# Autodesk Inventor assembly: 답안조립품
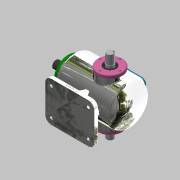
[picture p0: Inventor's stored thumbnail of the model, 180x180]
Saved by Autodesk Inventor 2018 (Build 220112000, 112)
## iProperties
Created: 2021-11
Part Number: 답안조립품
Material: 일반
Document SubType Name: Assembly
Designer: home
Author: home
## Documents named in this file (15)
- C:\Users\home\Desktop\711106V1040\답안조립품.iam
- C:\Users\home\Desktop\711106V1040\본체.ipt
- C:\Users\home\Desktop\711106V1040\슬라이드 커버.ipt
- C:\Users\home\Desktop\711106V1040\슬라이드.ipt
- C:\Users\home\Desktop\711106V1040\부시.ipt
- C:\Users\home\Desktop\711106V1040\상부커버.ipt
- C:\Users\home\Desktop\711106V1040\축 커버.ipt
- C:\Users\home\Desktop\711106V1040\베어링 6205.ipt
- 베어링 6205.ipt
- C:\Users\home\Desktop\711106V1040\축 커버_MIR.ipt
- C:\Users\home\Desktop\711106V1040\편심축.ipt
- C:\Users\home\Desktop\711106V1040\오일실.ipt
- 오일실.ipt
- C:\Users\home\Desktop\711106V1040\볼트 M4x0.7.ipt
- C:\Users\home\Desktop\711106V1040\육각머리볼트 M4.ipt
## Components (12 placed, 1 different names)
1. M4x0.7:9
2. M4x0.7:10
3. M4x0.7:11
4. M4x0.7:12
5. M4x0.7:1
6. M4x0.7:2
7. M4x0.7:3
8. M4x0.7:4
9. M4x0.7:13
10. M4x0.7:14
11. M4x0.7:15
12. M4x0.7:16
